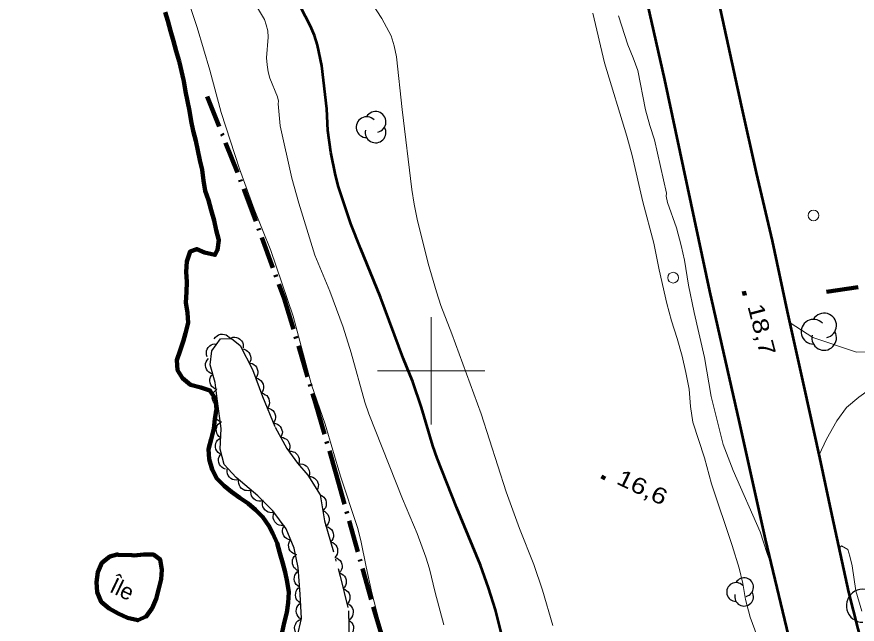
# Model space of a CAD drawing. Extents: x 355726 to 357533, y 5103782 to 5105258.
# Drawn here: x 356261.4 to 356339.7, y 5104876.4 to 5104933 of the extents above; entities that cross this region are included whole.
import ezdxf

# ---------------------------------------------------------------- set-up
doc = ezdxf.new("R2010")
doc.units = 0
doc.header["$LTSCALE"] = 0.6
for name, pattern in [('DASH_DOUBLE_DOT', [9.2, 5, -1.2, 0.3, -1.2, 0.3, -1.2]), ('DOT_DASHED', [7.7, 5, -1.2, 0.3, -1.2]), ('LONG_DASHED', [7.5, 6, -1.5])]:
    doc.linetypes.add(name, pattern=pattern)
for name, color, linetype, lineweight in [('1', 7, 'LONG_DASHED', 53), ('19', 7, 'Continuous', 13), ('2', 7, 'LONG_DASHED', 13), ('21', 7, 'LONG_DASHED', 35), ('3', 7, 'Continuous', 140), ('36', 7, 'Continuous', 13), ('4', 7, 'DASH_DOUBLE_DOT', 53), ('41', 7, 'DOT_DASHED', 90), ('44', 7, 'Continuous', 25), ('61', 7, 'Continuous', 13)]:
    doc.layers.add(name, color=color, linetype=linetype, lineweight=lineweight)
doc.layers.add('8', color=7, linetype='Continuous')

msp = doc.modelspace()

# ---------------------------------------------------------------- linework, layer by layer
at = {"layer": '1', "linetype": 'Continuous'}
msp.add_lwpolyline([(356307.02, 5104873.63), (356305.99, 5104877.74), (356305.36, 5104879.8), (356304.61, 5104881.9), (356302.38, 5104887.3), (356300.58, 5104891.86), (356300.15, 5104893.03), (356299.1, 5104896.61), (356298.29, 5104898.98), (356297.39, 5104901.2), (356295.3, 5104906.88), (356293.41, 5104911.44), (356292.53, 5104913.7), (356291.36, 5104917.15), (356291.08, 5104918.24), (356290.67, 5104920.38), (356290.39, 5104922.41), (356290.27, 5104924.42), (356289.82, 5104928.42), (356289.42, 5104930.34), (356289.12, 5104931.24), (356288.75, 5104932.11), (356284.22, 5104940.91)], dxfattribs=at)
at = {"layer": '19'}
for points in [[(356333.46, 5104904.47), (356335.57, 5104903.13), (356339.66, 5104901.75), (356344.4, 5104901.9), (356362.14, 5104903.9), (356364.98, 5104904.43), (356366.59, 5104905.18), (356367.46, 5104906.4), (356367.81, 5104907.32), (356367.57, 5104909.08)], [(356370.71, 5104887.21), (356369.36, 5104889.67), (356368.18, 5104891.13), (356366.64, 5104892.7), (356364.89, 5104894.48), (356363.12, 5104895.95), (356361.2, 5104897.23), (356359.04, 5104898.43), (356356.79, 5104899.34), (356354.75, 5104899.84), (356352.03, 5104900.3), (356349.21, 5104900.23), (356346.8, 5104900.11), (356344.3, 5104899.75), (356341.85, 5104899), (356339.86, 5104897.55), (356338.71, 5104896.58), (356337.81, 5104895.36), (356336.85, 5104893.66), (356336.17, 5104892.18)]]:
    msp.add_lwpolyline(points, dxfattribs=at)
at = {"layer": '2', "linetype": 'Continuous'}
for points in [[(356295.37, 5104875.84), (356294.48, 5104879.33), (356293.94, 5104881.74), (356293.46, 5104884.2), (356293.13, 5104885.41), (356291.56, 5104890.21), (356290.12, 5104895.04), (356288.85, 5104898.72), (356287.14, 5104905.11), (356285.05, 5104911.23), (356283.51, 5104915.07), (356282.13, 5104918.84), (356280.44, 5104924.08), (356279.38, 5104928.03), (356278.21, 5104931.99), (356276.55, 5104936.96)], [(356311.34, 5104876.28), (356310.37, 5104879.57), (356309.57, 5104881.97), (356308.25, 5104885.32), (356307.01, 5104888.74), (356304.66, 5104896), (356301.93, 5104903.45), (356300.9, 5104906.09), (356300.49, 5104907.37), (356299.73, 5104910), (356298.7, 5104914.15), (356298.42, 5104915.54), (356298.2, 5104916.92), (356297.3, 5104924.36), (356296.78, 5104929.26), (356296.57, 5104930.3), (356296.28, 5104931.22), (356295.4, 5104932.84), (356293.89, 5104935.21)], [(356301.18, 5104876.36), (356300.37, 5104879.36), (356299.86, 5104881.55), (356299.51, 5104882.66), (356298.7, 5104884.87), (356297.34, 5104888.09), (356294.21, 5104895.99), (356293.83, 5104897.09), (356292.54, 5104901.7), (356291.81, 5104904.08), (356290.55, 5104907.44), (356289.17, 5104910.78), (356287.68, 5104915.63), (356287.03, 5104917.95), (356285.94, 5104922.83), (356285.74, 5104924.88), (356285.78, 5104925.15), (356285.68, 5104925.53), (356284.98, 5104927.29), (356284.82, 5104927.88), (356284.71, 5104928.51), (356284.66, 5104929.18), (356284.81, 5104931.09), (356284.77, 5104931.69), (356284.64, 5104932.25), (356284.46, 5104932.76), (356283.74, 5104934)], [(356331.18, 5104873.17), (356329.74, 5104877.07), (356329.3, 5104878.7), (356329.05, 5104880.21), (356328.73, 5104881.62), (356328.07, 5104883.75), (356326.14, 5104889.49), (356325.49, 5104891.91), (356324.4, 5104895.23), (356324.19, 5104896.68), (356324.04, 5104898.3), (356323.74, 5104899.87), (356323.39, 5104901.38), (356322.94, 5104903.03), (356322.4, 5104904.66), (356321.97, 5104906.28), (356321.25, 5104909.43), (356320.76, 5104911.9), (356319.74, 5104915.76), (356318.74, 5104920.07), (356318.24, 5104921.86), (356316.15, 5104928.71), (356315.09, 5104933.34)], [(356331.73, 5104881.91), (356331.32, 5104882.98), (356330.67, 5104885.01), (356328.15, 5104890.74), (356327.22, 5104893.15), (356326.09, 5104897.62), (356325.48, 5104901.24), (356324.51, 5104905.45), (356324, 5104907.99), (356323.61, 5104910.33), (356323.3, 5104911.69), (356322.87, 5104913.34), (356322.04, 5104915.69), (356321.92, 5104916.3), (356321.95, 5104916.57), (356320.83, 5104921.53), (356320.39, 5104922.87), (356319.99, 5104924.33), (356319.26, 5104927.98), (356318.85, 5104929.16), (356318.34, 5104930.38), (356317.48, 5104933.08)], [(356340.14, 5104877.62), (356339.58, 5104879.51), (356339.25, 5104881.83), (356339.03, 5104882.76), (356338.83, 5104883.38), (356338.26, 5104883.7), (356338.05, 5104883.5)]]:
    msp.add_lwpolyline(points, dxfattribs=at)
at = {"layer": '21', "linetype": 'Continuous', "lineweight": 53}
for points in [[(356343.69, 5104859.4), (356342.43, 5104864.71), (356341.12, 5104870.84), (356338.94, 5104879.4), (356337.39, 5104886.54), (356336.22, 5104891.94), (356334.77, 5104898.54), (356333.22, 5104905.53), (356331.82, 5104912.12), (356330.33, 5104918.47), (356328.94, 5104924.74), (356327.72, 5104930.29), (356326.46, 5104936.17)], [(356320.14, 5104934.26), (356321.74, 5104927.11), (356325.96, 5104907.42), (356328.7, 5104895.22), (356331.15, 5104884.34), (356333.64, 5104873.84), (356336.2, 5104863.3), (356338.05, 5104856.13), (356339.08, 5104849.59), (356338.43, 5104846.12), (356336.08, 5104842.78), (356333.12, 5104840.96), (356329.6, 5104840.01), (356325.33, 5104839.34), (356320.5, 5104838.98), (356314.83, 5104838.82), (356308.31, 5104838.61), (356301.87, 5104838.38), (356293.36, 5104837.94), (356286.92, 5104837.59), (356279.79, 5104837.01), (356273.82, 5104836.36), (356265.12, 5104834.88), (356257.59, 5104833.43)]]:
    msp.add_lwpolyline(points, dxfattribs=at)
at = {"layer": '3'}
for p, q in [((356329.14, 5104907.43), (356329.24, 5104907.04)), ((356315.88, 5104890.16), (356316.24, 5104889.99))]:
    msp.add_line(p, q, dxfattribs=at)
at = {"layer": '36'}
for centre in [(356335.639, 5104914.49), (356322.559, 5104908.69)]:
    msp.add_circle(centre, 0.5, dxfattribs=at)
at = {"layer": '4', "linetype": 'Continuous', "lineweight": 90}
for points in [[(356278.79, 5104917.75), (356278.65, 5104918.73), (356278.46, 5104919.63), (356278.27, 5104920.53), (356278.08, 5104921.43), (356277.82, 5104922.37), (356277.63, 5104923.27), (356277.49, 5104924.24), (356277.3, 5104925.14), (356277.11, 5104926.04), (356276.96, 5104927.01), (356276.93, 5104927.13), (356276.55, 5104928.74), (356276.51, 5104928.85), (356276.25, 5104929.8), (356275.99, 5104930.74), (356275.72, 5104931.68), (356275.46, 5104932.62), (356275.23, 5104933.44)], [(356286.13, 5104875.65), (356286.32, 5104876.53), (356286.57, 5104877.49), (356286.69, 5104878.41), (356286.74, 5104879.38), (356286.59, 5104880.35), (356286.4, 5104881.25), (356286.17, 5104882.07), (356285.91, 5104883.01), (356285.65, 5104883.95), (356285.26, 5104884.86), (356284.87, 5104885.58), (356284.33, 5104886.38), (356283.63, 5104887.07), (356282.96, 5104887.64), (356282.17, 5104888.19), (356281.39, 5104888.73), (356280.72, 5104889.3), (356280.02, 5104889.99), (356279.59, 5104890.83), (356279.33, 5104891.77), (356279.26, 5104892.7), (356279.5, 5104893.65), (356279.74, 5104894.61), (356279.86, 5104895.53), (356279.99, 5104896.45), (356279.92, 5104897.39), (356279.38, 5104898.19), (356278.54, 5104898.46), (356277.58, 5104898.7), (356276.84, 5104899.32), (356276.37, 5104900.07), (356276.3, 5104901.01), (356276.62, 5104901.92), (356276.93, 5104902.83), (356277.12, 5104903.52), (356277.36, 5104904.47), (356277.29, 5104905.41), (356277.15, 5104906.38), (356277.19, 5104907.35), (356277.24, 5104908.31), (356277.17, 5104909.24), (356277.22, 5104910.21), (356277.54, 5104911.12), (356278.17, 5104911.36), (356278.89, 5104911.05), (356279.85, 5104910.81), (356280.1, 5104911.27), (356280.22, 5104912.19), (356279.96, 5104913.13), (356279.77, 5104914.03), (356279.51, 5104914.97), (356279.24, 5104915.91), (356278.94, 5104916.78), (356278.79, 5104917.75)]]:
    msp.add_lwpolyline(points, dxfattribs=at)
msp.add_lwpolyline([(356270.83, 5104882.86), (356270.75, 5104882.9), (356270.05, 5104882.7), (356269.32, 5104882.12), (356268.93, 5104881.25), (356268.81, 5104880.33), (356268.88, 5104879.39), (356269.26, 5104878.49), (356270, 5104877.87), (356270.83, 5104877.4), (356271.7, 5104877.01), (356272.66, 5104876.77), (356273.45, 5104877.12), (356273.99, 5104877.91), (356274.39, 5104878.78), (356274.63, 5104879.73), (356274.83, 5104880.61), (356274.91, 5104881.46), (356274.76, 5104882.43), (356274.12, 5104882.89), (356273.23, 5104882.9), (356272.3, 5104882.82), (356272.11, 5104882.83)], close=True, dxfattribs=at)
at = {"layer": '41'}
for points in [[(356279.14, 5104925.56), (356282.62, 5104916.77), (356286.31, 5104906.76), (356289.23, 5104896.99), (356291.12, 5104890.48), (356294.61, 5104878.01), (356298.89, 5104863.51), (356302.49, 5104854.05), (356305.32, 5104847.7)], [(356336.85, 5104907.36), (356344.39, 5104908.46), (356358.77, 5104911.85), (356380.85, 5104918.02)]]:
    msp.add_lwpolyline(points, dxfattribs=at)
at = {"layer": '44'}
for points in [[(356279.79, 5104902.98), (356279.9, 5104903.15), (356280.06, 5104903.28), (356280.19, 5104903.37), (356280.36, 5104903.42), (356280.55, 5104903.44), (356280.74, 5104903.41), (356280.89, 5104903.37), (356281.04, 5104903.28), (356281.18, 5104903.15), (356281.29, 5104903.01)], [(356279.13, 5104901.31), (356279.06, 5104901.5), (356279.06, 5104901.71), (356279.07, 5104901.87), (356279.14, 5104902.04), (356279.23, 5104902.19), (356279.37, 5104902.33), (356279.5, 5104902.43), (356279.66, 5104902.49), (356279.85, 5104902.52), (356280.03, 5104902.51)], [(356281.31, 5104903.07), (356281.51, 5104903.14), (356281.71, 5104903.14), (356281.87, 5104903.12), (356282.04, 5104903.05), (356282.19, 5104902.95), (356282.32, 5104902.8), (356282.41, 5104902.67), (356282.47, 5104902.51), (356282.5, 5104902.32), (356282.48, 5104902.14)], [(356282.37, 5104902.05), (356282.58, 5104902.02), (356282.76, 5104901.94), (356282.9, 5104901.85), (356283.02, 5104901.72), (356283.12, 5104901.57), (356283.17, 5104901.38), (356283.21, 5104901.22), (356283.19, 5104901.05), (356283.14, 5104900.87), (356283.05, 5104900.71)], [(356279.65, 5104899.71), (356279.45, 5104899.78), (356279.28, 5104899.89), (356279.16, 5104900.01), (356279.07, 5104900.16), (356279.01, 5104900.33), (356278.99, 5104900.52), (356278.99, 5104900.69), (356279.04, 5104900.85), (356279.13, 5104901.02), (356279.24, 5104901.16)], [(356283.11, 5104900.74), (356283.32, 5104900.69), (356283.49, 5104900.59), (356283.62, 5104900.49), (356283.72, 5104900.35), (356283.8, 5104900.18), (356283.84, 5104899.99), (356283.86, 5104899.83), (356283.82, 5104899.66), (356283.75, 5104899.48), (356283.64, 5104899.34)], [(356280.05, 5104898.27), (356279.85, 5104898.33), (356279.69, 5104898.45), (356279.57, 5104898.56), (356279.48, 5104898.71), (356279.41, 5104898.89), (356279.39, 5104899.08), (356279.39, 5104899.24), (356279.45, 5104899.41), (356279.53, 5104899.57), (356279.65, 5104899.71)], [(356283.64, 5104899.34), (356283.85, 5104899.29), (356284.02, 5104899.19), (356284.15, 5104899.09), (356284.26, 5104898.94), (356284.34, 5104898.78), (356284.37, 5104898.59), (356284.39, 5104898.43), (356284.35, 5104898.25), (356284.28, 5104898.08), (356284.18, 5104897.93)], [(356280.16, 5104896.76), (356279.97, 5104896.85), (356279.82, 5104896.99), (356279.72, 5104897.12), (356279.65, 5104897.28), (356279.61, 5104897.46), (356279.62, 5104897.65), (356279.64, 5104897.82), (356279.72, 5104897.98), (356279.83, 5104898.13), (356279.96, 5104898.25)], [(356284.17, 5104897.93), (356284.37, 5104897.89), (356284.55, 5104897.79), (356284.68, 5104897.7), (356284.79, 5104897.56), (356284.88, 5104897.39), (356284.92, 5104897.2), (356284.94, 5104897.04), (356284.91, 5104896.87), (356284.84, 5104896.7), (356284.74, 5104896.55)], [(356280.35, 5104895.27), (356280.16, 5104895.37), (356280.01, 5104895.51), (356279.91, 5104895.64), (356279.84, 5104895.8), (356279.81, 5104895.98), (356279.81, 5104896.17), (356279.84, 5104896.33), (356279.91, 5104896.49), (356280.02, 5104896.64), (356280.16, 5104896.76)], [(356284.74, 5104896.55), (356284.95, 5104896.5), (356285.13, 5104896.41), (356285.26, 5104896.31), (356285.37, 5104896.17), (356285.45, 5104896.01), (356285.49, 5104895.82), (356285.51, 5104895.66), (356285.48, 5104895.48), (356285.42, 5104895.31), (356285.32, 5104895.16)], [(356280.39, 5104893.78), (356280.22, 5104893.9), (356280.1, 5104894.07), (356280.02, 5104894.21), (356279.99, 5104894.38), (356279.98, 5104894.57), (356280.02, 5104894.76), (356280.07, 5104894.91), (356280.17, 5104895.05), (356280.31, 5104895.18), (356280.46, 5104895.28)], [(356285.28, 5104895.14), (356285.49, 5104895.12), (356285.68, 5104895.04), (356285.82, 5104894.96), (356285.94, 5104894.83), (356286.04, 5104894.68), (356286.1, 5104894.49), (356286.14, 5104894.33), (356286.12, 5104894.16), (356286.07, 5104893.98), (356285.99, 5104893.82)], [(356285.99, 5104893.82), (356286.2, 5104893.8), (356286.38, 5104893.72), (356286.53, 5104893.64), (356286.65, 5104893.51), (356286.75, 5104893.35), (356286.81, 5104893.17), (356286.84, 5104893.01), (356286.83, 5104892.84), (356286.78, 5104892.66), (356286.7, 5104892.5)], [(356280.32, 5104892.28), (356280.15, 5104892.4), (356280.03, 5104892.57), (356279.95, 5104892.71), (356279.92, 5104892.89), (356279.91, 5104893.07), (356279.95, 5104893.26), (356280, 5104893.41), (356280.1, 5104893.55), (356280.24, 5104893.68), (356280.39, 5104893.78)], [(356280.85, 5104890.85), (356280.65, 5104890.92), (356280.49, 5104891.03), (356280.37, 5104891.15), (356280.28, 5104891.3), (356280.21, 5104891.47), (356280.2, 5104891.66), (356280.2, 5104891.83), (356280.25, 5104891.99), (356280.34, 5104892.16), (356280.45, 5104892.29)], [(356286.74, 5104892.52), (356286.95, 5104892.53), (356287.14, 5104892.48), (356287.3, 5104892.42), (356287.43, 5104892.31), (356287.56, 5104892.17), (356287.64, 5104892), (356287.7, 5104891.85), (356287.71, 5104891.68), (356287.69, 5104891.49), (356287.63, 5104891.32)], [(356282.05, 5104889.85), (356281.85, 5104889.82), (356281.65, 5104889.85), (356281.49, 5104889.89), (356281.34, 5104889.99), (356281.2, 5104890.11), (356281.1, 5104890.27), (356281.02, 5104890.42), (356281, 5104890.59), (356281, 5104890.78), (356281.04, 5104890.95)], [(356287.64, 5104891.33), (356287.85, 5104891.35), (356288.05, 5104891.31), (356288.2, 5104891.26), (356288.35, 5104891.16), (356288.48, 5104891.03), (356288.58, 5104890.86), (356288.65, 5104890.72), (356288.67, 5104890.54), (356288.66, 5104890.36), (356288.61, 5104890.18)], [(356288.59, 5104890.17), (356288.8, 5104890.16), (356288.99, 5104890.1), (356289.14, 5104890.02), (356289.27, 5104889.9), (356289.38, 5104889.75), (356289.45, 5104889.58), (356289.5, 5104889.42), (356289.49, 5104889.24), (356289.46, 5104889.06), (356289.39, 5104888.9)], [(356283.22, 5104888.9), (356283.02, 5104888.84), (356282.81, 5104888.85), (356282.65, 5104888.87), (356282.49, 5104888.95), (356282.34, 5104889.06), (356282.22, 5104889.21), (356282.13, 5104889.34), (356282.08, 5104889.51), (356282.06, 5104889.7), (356282.08, 5104889.87)], [(356284.35, 5104887.92), (356284.15, 5104887.86), (356283.95, 5104887.87), (356283.79, 5104887.9), (356283.63, 5104887.97), (356283.48, 5104888.08), (356283.36, 5104888.23), (356283.27, 5104888.36), (356283.22, 5104888.53), (356283.2, 5104888.72), (356283.22, 5104888.9)], [(356289.66, 5104888.46), (356289.85, 5104888.37), (356290, 5104888.24), (356290.11, 5104888.12), (356290.19, 5104887.96), (356290.23, 5104887.78), (356290.23, 5104887.59), (356290.22, 5104887.42), (356290.15, 5104887.26), (356290.05, 5104887.11), (356289.92, 5104886.98)], [(356285.39, 5104886.83), (356285.18, 5104886.79), (356284.98, 5104886.81), (356284.82, 5104886.84), (356284.67, 5104886.93), (356284.52, 5104887.05), (356284.41, 5104887.21), (356284.33, 5104887.35), (356284.3, 5104887.52), (356284.29, 5104887.71), (356284.32, 5104887.88)], [(356286.25, 5104885.6), (356286.04, 5104885.59), (356285.85, 5104885.64), (356285.69, 5104885.7), (356285.56, 5104885.81), (356285.43, 5104885.95), (356285.35, 5104886.12), (356285.29, 5104886.28), (356285.28, 5104886.45), (356285.3, 5104886.64), (356285.36, 5104886.8)], [(356289.92, 5104886.98), (356290.11, 5104886.9), (356290.26, 5104886.76), (356290.37, 5104886.64), (356290.44, 5104886.48), (356290.49, 5104886.3), (356290.49, 5104886.11), (356290.47, 5104885.95), (356290.4, 5104885.78), (356290.3, 5104885.63), (356290.17, 5104885.5)], [(356286.91, 5104884.26), (356286.71, 5104884.3), (356286.53, 5104884.4), (356286.39, 5104884.49), (356286.29, 5104884.63), (356286.2, 5104884.8), (356286.16, 5104884.98), (356286.14, 5104885.15), (356286.17, 5104885.32), (356286.23, 5104885.49), (356286.33, 5104885.64)], [(356290.23, 5104885.52), (356290.43, 5104885.45), (356290.59, 5104885.33), (356290.71, 5104885.22), (356290.8, 5104885.07), (356290.87, 5104884.9), (356290.89, 5104884.71), (356290.89, 5104884.54), (356290.83, 5104884.37), (356290.75, 5104884.21), (356290.63, 5104884.07)], [(356287.49, 5104882.88), (356287.29, 5104882.92), (356287.11, 5104883.01), (356286.98, 5104883.11), (356286.87, 5104883.25), (356286.78, 5104883.41), (356286.74, 5104883.6), (356286.72, 5104883.76), (356286.75, 5104883.94), (356286.81, 5104884.11), (356286.91, 5104884.26)], [(356290.63, 5104884.07), (356290.83, 5104884.01), (356291, 5104883.89), (356291.12, 5104883.78), (356291.21, 5104883.62), (356291.27, 5104883.45), (356291.29, 5104883.26), (356291.29, 5104883.1), (356291.24, 5104882.93), (356291.15, 5104882.77), (356291.04, 5104882.63)], [(356287.68, 5104881.37), (356287.49, 5104881.45), (356287.33, 5104881.58), (356287.22, 5104881.7), (356287.14, 5104881.86), (356287.09, 5104882.03), (356287.08, 5104882.22), (356287.09, 5104882.39), (356287.15, 5104882.55), (356287.25, 5104882.71), (356287.38, 5104882.84)], [(356291.04, 5104882.63), (356291.24, 5104882.56), (356291.4, 5104882.44), (356291.52, 5104882.33), (356291.61, 5104882.18), (356291.68, 5104882.01), (356291.7, 5104881.82), (356291.7, 5104881.65), (356291.64, 5104881.49), (356291.56, 5104881.32), (356291.44, 5104881.18)], [(356287.75, 5104879.87), (356287.57, 5104879.97), (356287.43, 5104880.12), (356287.34, 5104880.26), (356287.28, 5104880.42), (356287.25, 5104880.61), (356287.27, 5104880.8), (356287.3, 5104880.96), (356287.39, 5104881.11), (356287.5, 5104881.26), (356287.64, 5104881.37)], [(356291.45, 5104881.19), (356291.65, 5104881.11), (356291.81, 5104880.99), (356291.93, 5104880.87), (356292.01, 5104880.72), (356292.07, 5104880.54), (356292.08, 5104880.35), (356292.08, 5104880.19), (356292.02, 5104880.02), (356291.93, 5104879.86), (356291.8, 5104879.73)], [(356287.84, 5104878.37), (356287.67, 5104878.48), (356287.53, 5104878.63), (356287.44, 5104878.77), (356287.38, 5104878.94), (356287.36, 5104879.12), (356287.38, 5104879.31), (356287.41, 5104879.47), (356287.5, 5104879.62), (356287.62, 5104879.76), (356287.76, 5104879.87)], [(356291.8, 5104879.73), (356292, 5104879.65), (356292.16, 5104879.53), (356292.28, 5104879.41), (356292.36, 5104879.26), (356292.42, 5104879.08), (356292.43, 5104878.89), (356292.43, 5104878.73), (356292.37, 5104878.56), (356292.28, 5104878.4), (356292.15, 5104878.27)], [(356287.92, 5104876.88), (356287.74, 5104876.98), (356287.61, 5104877.13), (356287.52, 5104877.27), (356287.46, 5104877.44), (356287.44, 5104877.62), (356287.46, 5104877.81), (356287.49, 5104877.97), (356287.58, 5104878.12), (356287.7, 5104878.26), (356287.84, 5104878.37)], [(356292.29, 5104878.29), (356292.46, 5104878.17), (356292.59, 5104878.02), (356292.68, 5104877.88), (356292.73, 5104877.71), (356292.75, 5104877.53), (356292.72, 5104877.34), (356292.68, 5104877.18), (356292.59, 5104877.03), (356292.46, 5104876.89), (356292.32, 5104876.79)], [(356287.58, 5104875.41), (356287.44, 5104875.56), (356287.34, 5104875.75), (356287.29, 5104875.9), (356287.28, 5104876.08), (356287.31, 5104876.26), (356287.38, 5104876.44), (356287.46, 5104876.58), (356287.58, 5104876.71), (356287.74, 5104876.81), (356287.9, 5104876.88)], [(356292.32, 5104876.79), (356292.49, 5104876.67), (356292.62, 5104876.52), (356292.71, 5104876.38), (356292.76, 5104876.21), (356292.78, 5104876.03), (356292.75, 5104875.84), (356292.71, 5104875.68), (356292.62, 5104875.53), (356292.5, 5104875.39), (356292.35, 5104875.29)]]:
    msp.add_lwpolyline(points, dxfattribs=at)
at = {"layer": '44', "linetype": 'DOT_DASHED'}
msp.add_lwpolyline([(356287.53, 5104875.19), (356287.92, 5104876.95), (356287.8, 5104879.2), (356287.62, 5104881.68), (356287.24, 5104883.48), (356286.48, 5104885.29), (356285.24, 5104886.97), (356283.84, 5104888.36), (356281.84, 5104890.08), (356280.73, 5104891.29), (356280.34, 5104892.7), (356280.43, 5104894.63), (356280.1, 5104897.2), (356279.87, 5104898.91), (356279.41, 5104900.56), (356279.55, 5104901.87), (356280.38, 5104902.99), (356281.39, 5104903.01), (356282.21, 5104902.36), (356283.34, 5104900.14), (356284.3, 5104897.61), (356285.48, 5104894.77), (356286.54, 5104892.79), (356287.56, 5104891.42), (356288.51, 5104890.3), (356289.66, 5104888.46), (356290.08, 5104886.04), (356291.53, 5104880.87), (356292.3, 5104877.66), (356292.41, 5104872.25)], dxfattribs=at)
at = {"layer": '44'}
for centre, radius, start, end in [((356293.991, 5104922.712), 0.97, 44.11537, 269.80396), ((356294.825, 5104923.197), 0.97, 282.26917, 149.72626), ((356294.825, 5104922.227), 0.97, 166.93686, 29.62122), ((356335.641, 5104903.656), 1.151, 44.11537, 269.80396), ((356336.631, 5104904.232), 1.151, 282.26917, 149.72626), ((356336.631, 5104903.081), 1.151, 166.93686, 29.62122), ((356329.175, 5104879.847), 0.875, 282.26917, 149.72626), ((356328.423, 5104879.41), 0.875, 44.11537, 269.80396), ((356329.175, 5104878.973), 0.875, 166.93686, 29.62122), ((356340.248, 5104878.125), 1.542, 44.11537, 269.80396)]:
    msp.add_arc(centre, radius, start, end, dxfattribs=at)
at = {"layer": '61'}
for p, q in [((356300, 5104895), (356300, 5104905)), ((356295, 5104900), (356305, 5104900))]:
    msp.add_line(p, q, dxfattribs=at)

# ---------------------------------------------------------------- texts
at = {"layer": '3', "width": 1.25}
for s, rotation, p in [('18,7   ', 284.583, (356329.48, 5104906.03)), ('16,6   ', 334.423, (356317.17, 5104889.54))]:
    msp.add_text(s, height=1.5, rotation=rotation, dxfattribs=at).set_placement(p)
at = {"layer": '8'}
msp.add_text('Île', height=1.5, rotation=334.42, dxfattribs=at).set_placement((356269.94, 5104879.46))

doc.saveas('drawing.dxf')
